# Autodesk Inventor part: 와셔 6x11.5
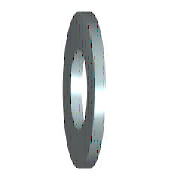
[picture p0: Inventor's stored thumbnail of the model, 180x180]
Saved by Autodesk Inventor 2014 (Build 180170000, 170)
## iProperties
IsCustomPart: 1
Created: 2012-02
Part Number: 와셔 6x11.5
Material: 강철, 연강
Description: 평면 와셔
Document SubType Name: Modeling
Standard: KS B 1326
Designer: mduedu
Standards Organization: KS
Language: ko-KR
Size Designation: 6x11.5
Categories: <MemberInstance><Categories><Category DisplayName="조임쇠" InternalName="e4da775c-781d-43d5-af7c-5136215cf5a6" Mnemonic="FSTN"><Category DisplayName="와셔" InternalN
Density: 1 g/cm^3
Appearance: 주황색
Author: mduedu
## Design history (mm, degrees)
sketch "스케치"
  geometry: C1 r 5.75 at (0, 0); C2 r 3.2 at (0, 0); 1 further point
  constraints: 2 centre point, 2 coincident
  dimensions: "d0" = 6.4 diameter of C2 (= SD1); "d1" = 11.5 diameter of C1 (= SD2)
extrude "본체" new body sketch "스케치" distance "d2" = 1.6 (= SD); taper "d3" = 0 deg
workaxis "Work Axis1"
workplane "Work Plane1"
body "Solid1"
other parameters: "SD1" = 6.4 [user parameter; used in 1 equation term], "SD2" = 11.5 [user parameter; used in 1 equation term], "SD" = 1.6 [user parameter; used in 1 equation term], "d4" = 0, "d5" = 0, "d6" = 0, "d7" = 0, "NND" = 6 [user parameter]
